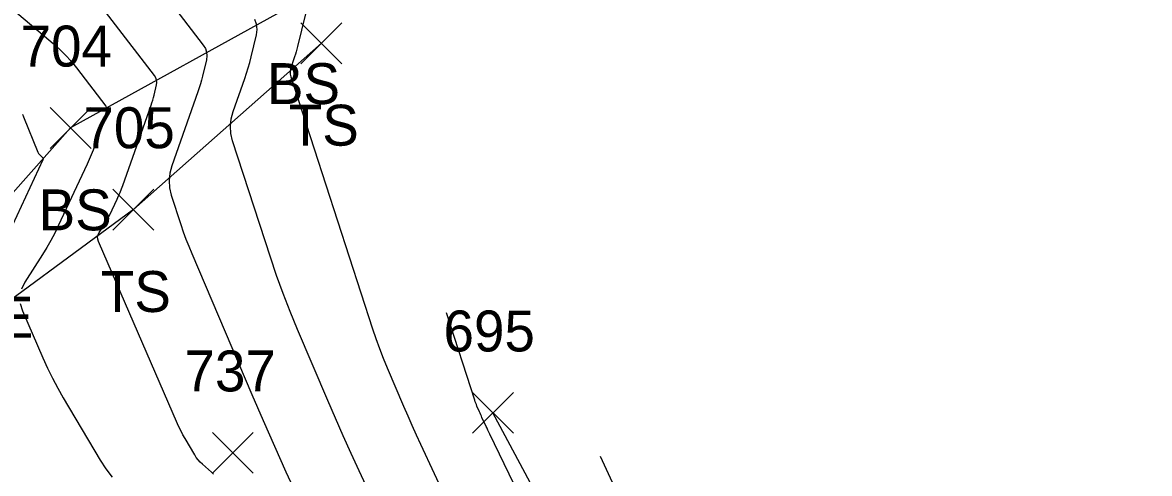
# Model space of a CAD drawing. Extents: x 1592612 to 1596497, y 111838 to 113741.
# Drawn here: x 1592870.8 to 1592925.8, y 113526.4 to 113548.4 of the extents above; entities that cross this region are included whole.
import ezdxf

# ---------------------------------------------------------------- set-up
doc = ezdxf.new("R2010")
doc.units = 0
for name, color, linetype in [('L_A', 7, 'Continuous'), ('L_I', 7, 'Continuous'), ('L_TIC', 7, 'Continuous'), ('LELB', 7, 'Continuous'), ('LSOGCMA', 7, 'Continuous'), ('LSOGCMI', 7, 'Continuous')]:
    doc.layers.add(name, color=color, linetype=linetype)

msp = doc.modelspace()

# ---------------------------------------------------------------- linework, layer by layer
at = {"layer": 'L_TIC'}
for points in [[(1592884.411, 113546.376), (1592886.411, 113548.376)], [(1592886.411, 113546.376), (1592884.411, 113548.376)], [(1592872.166, 113542.239), (1592874.166, 113544.239)], [(1592874.166, 113542.239), (1592872.166, 113544.239)], [(1592875.234, 113538.25), (1592877.234, 113540.25)], [(1592877.234, 113538.25), (1592875.234, 113540.25)], [(1592892.782, 113528.323), (1592894.782, 113530.323)], [(1592894.782, 113528.323), (1592892.782, 113530.323)], [(1592880.088, 113526.371), (1592882.088, 113528.371)], [(1592882.088, 113526.371), (1592880.088, 113528.371)]]:
    msp.add_lwpolyline(points, dxfattribs=at)
at = {"layer": 'LELB'}
for points in [[(1592884.313, 113549.407), (1592873.166, 113543.239), (1592866.23, 113535.449), (1592862.822, 113524.774)], [(1592885.411, 113547.376), (1592876.234, 113539.25), (1592867.617, 113532.911), (1592863.38, 113520.43), (1592865.405, 113513.944), (1592869.075, 113508.737), (1592880.629, 113500.08), (1592889.409, 113493.364), (1592892.469, 113484.552), (1592893.995, 113472.176), (1592892.484, 113467.779), (1592891.718, 113461.24)], [(1592918.957, 113461.096), (1592928.472, 113467.665), (1592923.872, 113481.628), (1592916.743, 113497.854), (1592906.203, 113506.134), (1592893.782, 113529.323)]]:
    msp.add_lwpolyline(points, dxfattribs=at)
at = {"layer": 'LSOGCMA'}
for points in [[(1592880.149, 113526.33), (1592880.044, 113526.431), (1592879.599, 113526.82), (1592879.492, 113526.921), (1592879.394, 113527.029), (1592879.305, 113527.145), (1592879.226, 113527.268), (1592878.755, 113528.065), (1592878.654, 113528.242), (1592878.559, 113528.422), (1592878.469, 113528.604), (1592878.386, 113528.79), (1592874.529, 113537.691), (1592874.493, 113537.805), (1592874.488, 113537.917), (1592874.511, 113538.027), (1592874.564, 113538.134), (1592874.836, 113538.558), (1592874.902, 113538.666), (1592874.965, 113538.775), (1592875.024, 113538.886), (1592875.079, 113538.999), (1592875.433, 113539.762), (1592875.508, 113539.928), (1592875.579, 113540.095), (1592875.646, 113540.264), (1592875.709, 113540.435), (1592877.099, 113544.355), (1592877.14, 113544.476), (1592877.178, 113544.598), (1592877.212, 113544.722), (1592877.243, 113544.846), (1592877.361, 113545.344), (1592877.377, 113545.465), (1592877.367, 113545.581), (1592877.329, 113545.692), (1592877.265, 113545.796), (1592873.296, 113550.977)], [(1592899.015, 113527.211), (1592907.029, 113509.856)]]:
    msp.add_lwpolyline(points, dxfattribs=at)
at = {"layer": 'LSOGCMI'}
for points in [[(1592872.378, 113556.771), (1592879.646, 113547.282), (1592879.748, 113547.117), (1592879.808, 113546.943), (1592879.825, 113546.759), (1592879.799, 113546.567), (1592879.612, 113545.779), (1592879.563, 113545.583), (1592879.509, 113545.389), (1592879.449, 113545.196), (1592879.384, 113545.004), (1592878.103, 113541.394), (1592878.008, 113541.037), (1592877.972, 113540.68), (1592877.998, 113540.322), (1592878.084, 113539.964), (1592878.55, 113538.527), (1592878.67, 113538.169), (1592878.798, 113537.815), (1592878.934, 113537.463), (1592879.078, 113537.114), (1592882.016, 113530.212), (1592882.561, 113528.948), (1592883.116, 113527.689), (1592883.681, 113526.435), (1592884.258, 113525.186)], [(1592867.788, 113551.187), (1592872.321, 113547.364), (1592872.627, 113547.092), (1592872.917, 113546.804), (1592873.191, 113546.501), (1592873.449, 113546.182), (1592874.883, 113544.31), (1592874.91, 113544.266), (1592874.926, 113544.22), (1592874.93, 113544.172), (1592874.923, 113544.121), (1592874.874, 113543.912), (1592874.861, 113543.86), (1592874.846, 113543.808), (1592874.831, 113543.757), (1592874.813, 113543.706), (1592874.347, 113542.392), (1592874.261, 113542.157), (1592874.169, 113541.925), (1592874.072, 113541.694), (1592873.969, 113541.466), (1592872.568, 113538.454), (1592872.393, 113538.095), (1592872.207, 113537.742), (1592872.009, 113537.396), (1592871.799, 113537.056), (1592870.937, 113535.709), (1592870.768, 113535.369)], [(1592884.629, 113548.822), (1592884.249, 113547.215), (1592884.217, 113547.09), (1592884.182, 113546.965), (1592884.144, 113546.842), (1592884.102, 113546.72), (1592883.929, 113546.232), (1592883.896, 113546.11), (1592883.884, 113545.987), (1592883.893, 113545.865), (1592883.923, 113545.742), (1592887.911, 113533.436), (1592888.074, 113532.953), (1592888.247, 113532.474), (1592888.431, 113531.999), (1592888.625, 113531.528), (1592889.424, 113529.652), (1592889.625, 113529.184), (1592889.831, 113528.718), (1592890.041, 113528.253), (1592890.254, 113527.79), (1592891.589, 113524.929)], [(1592889.817, 113520.998), (1592887.256, 113526.488), (1592886.861, 113527.344), (1592886.473, 113528.203), (1592886.093, 113529.066), (1592885.72, 113529.932), (1592884.243, 113533.402), (1592883.883, 113534.274), (1592883.543, 113535.152), (1592883.223, 113536.038), (1592882.923, 113536.931), (1592881.079, 113542.618), (1592880.993, 113542.976), (1592880.968, 113543.333), (1592881.003, 113543.689), (1592881.099, 113544.045), (1592881.669, 113545.653), (1592881.758, 113545.915), (1592881.84, 113546.179), (1592881.914, 113546.445), (1592881.982, 113546.713), (1592882.237, 113547.79), (1592882.272, 113548.053), (1592882.249, 113548.304), (1592882.167, 113548.542)], [(1592870.817, 113543.899), (1592870.824, 113543.892), (1592870.831, 113543.884), (1592870.836, 113543.875), (1592870.839, 113543.866), (1592870.853, 113543.827), (1592870.856, 113543.817), (1592870.859, 113543.808), (1592870.863, 113543.798), (1592870.867, 113543.789), (1592871.566, 113542.064), (1592871.584, 113542.026), (1592871.605, 113541.991), (1592871.631, 113541.959), (1592871.66, 113541.929), (1592871.785, 113541.815), (1592871.81, 113541.785), (1592871.823, 113541.753), (1592871.824, 113541.719), (1592871.812, 113541.682), (1592869.904, 113537.58)], [(1592870.711, 113534.666), (1592870.824, 113534.303), (1592871.816, 113532.012), (1592872.042, 113531.512), (1592872.283, 113531.02), (1592872.54, 113530.535), (1592872.812, 113530.059), (1592874.612, 113527.013), (1592874.889, 113526.583), (1592875.197, 113526.18)], [(1592903.752, 113507.333), (1592893.632, 113528.285), (1592893.587, 113528.379), (1592893.542, 113528.473), (1592893.497, 113528.568), (1592893.453, 113528.663), (1592893.252, 113529.092), (1592893.22, 113529.162), (1592893.189, 113529.232), (1592893.158, 113529.302), (1592893.128, 113529.372), (1592893.008, 113529.654), (1592892.978, 113529.725), (1592892.951, 113529.796), (1592892.925, 113529.868), (1592892.9, 113529.941), (1592891.517, 113534.207)]]:
    msp.add_lwpolyline(points, dxfattribs=at)

# ---------------------------------------------------------------- texts
at = {"layer": 'L_A'}
for s, p in [('BS', (1592882.754, 113544.407)), ('TS', (1592883.82, 113542.376)), ('BS', (1592871.607, 113538.239)), ('TS', (1592874.644, 113534.25)), ('STONE', (1592862.143, 113532.992))]:
    msp.add_text(s, height=2, dxfattribs=at).set_placement(p)
at = {"layer": 'L_I'}
for s, p in [('704', (1592870.725, 113546.239)), ('705', (1592873.793, 113542.25)), ('695', (1592891.373, 113532.323)), ('737', (1592878.725, 113530.371))]:
    msp.add_text(s, height=2, dxfattribs=at).set_placement(p)

doc.saveas('drawing.dxf')
